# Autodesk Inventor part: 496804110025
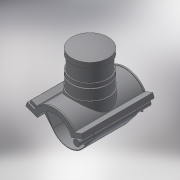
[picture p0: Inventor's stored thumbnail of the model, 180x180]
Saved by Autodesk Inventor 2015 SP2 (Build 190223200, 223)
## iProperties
Created: 2017-07
Part Number: 496804110025
Material: Generic
Description: PLASSON BALLOON SADDLE 110-2.1/2"
Document SubType Name: Modeling
Designer: KIM
Density: 1 g/cm^3
Appearance: Default
Author: KIM
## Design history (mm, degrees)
derived "496804.ipt"
feature "Solid1::496804.ipt"
feature "Solid2::496804.ipt"
tag "TaggingFeature1"
body "Solid1"
body "Solid2"
other parameters: "d1" = 129.8, "d4" = 176, "d5" = 0, "d40" = 67.496, "d96" = 132.396, "d97" = 3.52, "d98" = 0, "d120" = 140 deg, "d121" = 24.228, "d122" = 20 deg, "d123" = 259.6, "d124" = 77.88, "d126" = 0, "d143" = 113.3, "d145" = 15.23077, "d149" = 1.65, "d150" = 16.75385, "d153" = 176, "d154" = 0, "d159" = 3.96, "d161" = 1.65, "d162" = 105.6, "d163" = 0, "d164" = 55, "d168" = 68.31579, "d170" = 1.65, "d172" = 0, "d173" = 1, "d175" = 55, "d176" = 20 deg, "d177" = 13.2, "d180" = 0, "d185" = 57.2, "d186" = 57.2, "d187" = 64.9, "d188" = 5.94, "d190" = 0, "d191" = 103.84, "d193" = 3.96, "d194" = 4.4, "d195" = 90 deg, "d197" = 0, "d199" = 0, "d200" = 105, "d201" = 1, "d203" = 94.5, "d204" = 97.65, "d205" = 85.5, "d206" = 1.8, "d207" = 52.5, "d208" = 42, "d209" = 84, "d210" = 15.75, "d214" = 129.8, "d216" = 0, "d219" = 5.5, "d220" = 15.98, "d221" = 8 deg, "d223" = 16.2125, "d224" = 8.10625, "d226" = 0, "d227" = -17.6, "d228" = 1.98, "d229" = 24.2, "H_" = 105, "L_" = 176, "d_t" = 6, "d148" = 1.65, "d160" = 1.65, "d169" = 1.65, "d192" = 3.96, "d222" = 20.26562
